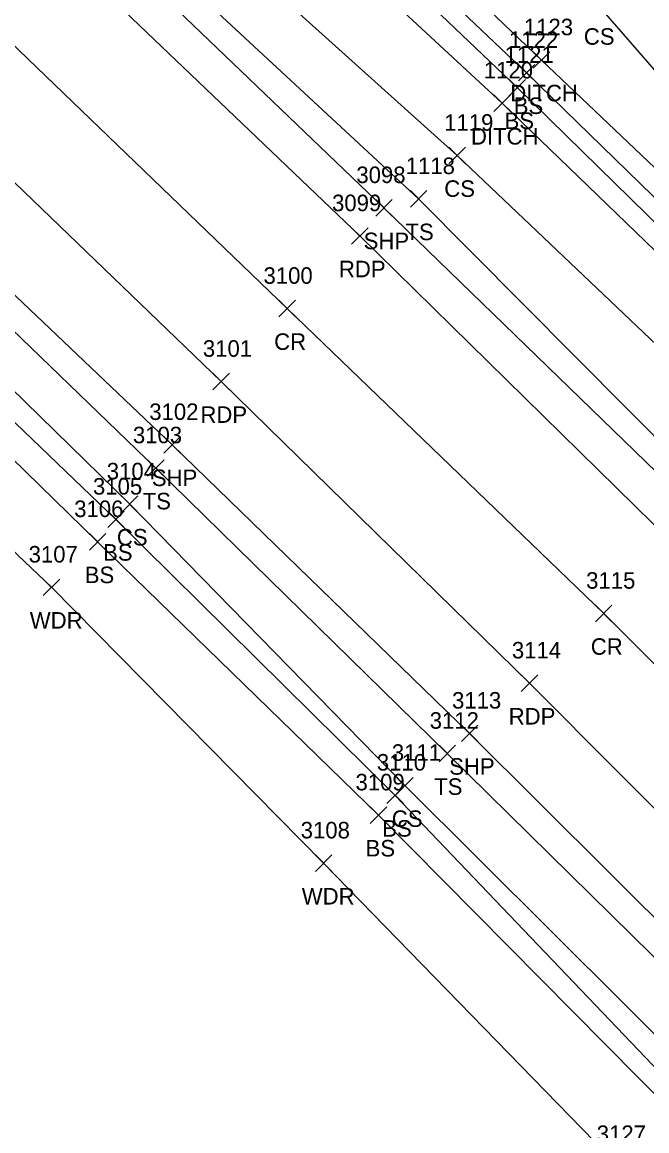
# Model space of a CAD drawing. Extents: x 1647574 to 1652703, y 212895 to 228670.
# Drawn here: x 1649743 to 1649818.5, y 226264.6 to 226398.8 of the extents above; entities that cross this region are included whole.
import ezdxf

# ---------------------------------------------------------------- set-up
doc = ezdxf.new("R2010")
doc.units = 0
for name, color, linetype in [('D_A', 7, 'Continuous'), ('D_I', 7, 'Continuous'), ('D_TIC', 7, 'Continuous'), ('DD', 7, 'Continuous'), ('L_A', 7, 'Continuous'), ('L_I', 7, 'Continuous'), ('L_TIC', 7, 'Continuous'), ('LAWA', 7, 'Continuous'), ('LELB', 7, 'Continuous'), ('P_A', 7, 'Continuous'), ('P_I', 7, 'Continuous'), ('P_TIC', 7, 'Continuous'), ('PET', 7, 'Continuous'), ('PRC', 7, 'Continuous'), ('PSP', 7, 'Continuous')]:
    doc.layers.add(name, color=color, linetype=linetype)

msp = doc.modelspace()

# ---------------------------------------------------------------- linework, layer by layer
at = {"layer": 'D_TIC'}
for points in [[(1649804.8, 226393.2), (1649806.8, 226395.2)], [(1649806.8, 226393.2), (1649804.8, 226395.2)], [(1649800.03, 226387.97), (1649802.03, 226389.97)], [(1649802.03, 226387.97), (1649800.03, 226389.97)]]:
    msp.add_lwpolyline(points, dxfattribs=at)
at = {"layer": 'DD'}
for points in [[(1649866.07, 226326.34), (1649834.51, 226356.66), (1649801.03, 226388.97), (1649771.25, 226416.61), (1649755.64, 226431), (1649757.57, 226433.02), (1649758.52, 226434.35), (1649760.18, 226436.47)], [(1649866.07, 226326.34), (1649867.38, 226328.16), (1649869, 226330.3), (1649871.11, 226331.79), (1649839.7, 226361.95), (1649805.8, 226394.2), (1649776.78, 226421.97), (1649760.18, 226436.47)]]:
    msp.add_lwpolyline(points, dxfattribs=at)
at = {"layer": 'L_TIC'}
for points in [[(1649803, 226391.67), (1649805, 226393.67)], [(1649805, 226391.67), (1649803, 226393.67)], [(1649801.88, 226389.85), (1649803.88, 226391.85)], [(1649803.88, 226389.85), (1649801.88, 226391.85)], [(1649794.6, 226381.64), (1649796.6, 226383.64)], [(1649796.6, 226381.64), (1649794.6, 226383.64)], [(1649789.94, 226376.4), (1649791.94, 226378.4)], [(1649791.94, 226376.4), (1649789.94, 226378.4)], [(1649758.16, 226343.82), (1649760.16, 226345.82)], [(1649760.16, 226343.82), (1649758.16, 226345.82)], [(1649755, 226339.45), (1649757, 226341.45)], [(1649757, 226339.45), (1649755, 226341.45)], [(1649753.34, 226337.61), (1649755.34, 226339.61)], [(1649755.34, 226337.61), (1649753.34, 226339.61)], [(1649751.12, 226334.89), (1649753.12, 226336.89)], [(1649753.12, 226334.89), (1649751.12, 226336.89)], [(1649745.55, 226329.39), (1649747.55, 226331.39)], [(1649747.55, 226329.39), (1649745.55, 226331.39)], [(1649793.41, 226309.27), (1649795.41, 226311.27)], [(1649795.41, 226309.27), (1649793.41, 226311.27)], [(1649787.1, 226304.21), (1649789.1, 226306.21)], [(1649789.1, 226304.21), (1649787.1, 226306.21)], [(1649788.26, 226305.39), (1649790.26, 226307.39)], [(1649790.26, 226305.39), (1649788.26, 226307.39)], [(1649785.09, 226301.81), (1649787.09, 226303.81)], [(1649787.09, 226301.81), (1649785.09, 226303.81)], [(1649778.45, 226296), (1649780.45, 226298)], [(1649780.45, 226296), (1649778.45, 226298)]]:
    msp.add_lwpolyline(points, dxfattribs=at)
at = {"layer": 'LAWA'}
msp.add_lwpolyline([(1649564.01, 226501.21), (1649600.78, 226471.1), (1649629.15, 226441.1), (1649657.11, 226422.45), (1649662.3, 226420.26), (1649668.81, 226414.71), (1649676.02, 226404.08), (1649707.48, 226367.52), (1649746.55, 226330.39), (1649779.45, 226297), (1649815.18, 226260.26), (1649850.99, 226223.94), (1649889.13, 226181.22), (1649919.64, 226149.68), (1649954.03, 226112.54), (1649976.77, 226080.57), (1650010.23, 226040.33), (1650031.5, 226013.99), (1650047.73, 225988.88)], dxfattribs=at)
at = {"layer": 'LELB'}
for points in [[(1650145.31, 225996.12), (1650126.11, 226017.39), (1650101.66, 226047.08), (1650074.02, 226078.27), (1650048.35, 226107.52), (1650011.02, 226148.89), (1649978.29, 226184.76), (1649948.32, 226216.56), (1649918.31, 226248.62), (1649881.09, 226286.67), (1649854.51, 226315.1), (1649822.53, 226345.57), (1649790.94, 226377.4), (1649759.46, 226406.66), (1649722.98, 226440.72), (1649699.36, 226464.18), (1649670.41, 226492.35), (1649633.05, 226526.99), (1649601.72, 226556.3), (1649565.56, 226590.44)], [(1649576.43, 226518.4), (1649614.41, 226482.98), (1649642.41, 226455.9), (1649685.38, 226415.67), (1649721.92, 226380.74), (1649759.16, 226344.82), (1649794.41, 226310.27), (1649829.09, 226276.12), (1649866.9, 226238.21), (1649900.81, 226202.84), (1649937.1, 226163.93), (1649969.44, 226128.19), (1649998.01, 226097.17), (1650029.45, 226060.68), (1650045.36, 226034.05), (1650069.99, 226009.77), (1650092.51, 225984.63), (1650111.94, 225960.02)], [(1649572.06, 226513.32), (1649610.08, 226478.23), (1649638.08, 226450.58), (1649682.17, 226412.39), (1649718, 226377.59), (1649756, 226340.45), (1649789.26, 226306.39), (1649824.84, 226270.98), (1649865.01, 226237.13), (1649898.41, 226199.96), (1649935.32, 226162.62), (1649968.54, 226127.19), (1649995.98, 226095.51), (1650026.38, 226057.31)], [(1649570.19, 226510.51), (1649608.23, 226476.35), (1649636.57, 226449.06), (1649663.19, 226421.28), (1649670.48, 226414.78), (1649679.22, 226408.18), (1649715.79, 226375.57), (1649754.34, 226338.61), (1649788.1, 226305.21), (1649822.67, 226268.96), (1649860.5, 226231.77), (1649895.97, 226193.57), (1649929.13, 226157.26), (1649962.02, 226120.66), (1649988.9, 226089.08), (1650019.8, 226051.49), (1650041.89, 226022.86), (1650059.37, 225999.62), (1650079.66, 225974.03), (1650096.25, 225946.36)], [(1650034.79, 226165.59), (1650004.25, 226206.53), (1649976.89, 226237.09), (1649942.39, 226273.76), (1649905.43, 226305.34), (1649874.8, 226336.52), (1649843.44, 226365.42), (1649812.48, 226401.05), (1649784.9, 226430.14), (1649744.52, 226461.95), (1649720.63, 226485.58), (1649711.56, 226477.85), (1649711.58, 226477.78), (1649705.42, 226471.73), (1649700.93, 226467.69), (1649709.73, 226458.24)], [(1650148.97, 226010.88), (1650139.27, 226026.59), (1650113.43, 226057), (1650088.3, 226087.98), (1650061.28, 226120.08), (1650026.24, 226159.75), (1649992.44, 226196.13), (1649963.33, 226228.07), (1649931.94, 226262.56), (1649896.29, 226297.95), (1649867.38, 226328.16), (1649836.11, 226358.29), (1649802.88, 226390.85), (1649773.49, 226418.93), (1649757.57, 226433.02), (1649733.38, 226449.67), (1649721.38, 226464.7), (1649717.89, 226468.09), (1649721.1, 226472.27), (1649725.43, 226467.47)], [(1650148.97, 226010.88), (1650154.49, 226019.63), (1650146.18, 226030.47), (1650117.14, 226060.39), (1650092.92, 226091.65), (1650065.04, 226122.85), (1650030.31, 226163.04), (1649996.06, 226198.8), (1649967.82, 226231.08), (1649935.01, 226265.64), (1649900.92, 226301.66), (1649869, 226330.3), (1649837.58, 226359.92), (1649804, 226392.67), (1649775.11, 226420.09), (1649758.52, 226434.35), (1649738.4, 226455.19), (1649725.43, 226467.47)], [(1650055.12, 226113.82), (1650017.96, 226153.32), (1649984.83, 226189.55), (1649957.12, 226222.67), (1649926.78, 226257.2), (1649885.72, 226290.18), (1649859.03, 226319.45), (1649828.58, 226351.31), (1649795.6, 226382.64), (1649764.56, 226410.62), (1649728.45, 226444.97), (1649709.73, 226458.24)], [(1649668.81, 226414.71), (1649677.68, 226406.85), (1649713.8, 226373.3), (1649752.12, 226335.89), (1649786.09, 226302.81), (1649821.42, 226267.05), (1649857.98, 226229.57), (1649894.19, 226191.19), (1649927.6, 226155.83), (1649960.21, 226119.33), (1649987.22, 226087.32), (1650018.26, 226049.98), (1650039.74, 226020.41), (1650056.73, 225997.13), (1650074.38, 225969.86), (1650089, 225939.93)]]:
    msp.add_lwpolyline(points, dxfattribs=at)
at = {"layer": 'P_TIC'}
for points in [[(1649785.75, 226375.31), (1649787.75, 226377.31)], [(1649787.75, 226375.31), (1649785.75, 226377.31)], [(1649782.82, 226371.91), (1649784.82, 226373.91)], [(1649784.82, 226371.91), (1649782.82, 226373.91)], [(1649774.04, 226363.12), (1649776.04, 226365.12)], [(1649776.04, 226363.12), (1649774.04, 226365.12)], [(1649766.06, 226354.29), (1649768.06, 226356.29)], [(1649768.06, 226354.29), (1649766.06, 226356.29)], [(1649760.14, 226346.64), (1649762.14, 226348.64)], [(1649762.14, 226346.64), (1649760.14, 226348.64)], [(1649812.32, 226326.22), (1649814.32, 226328.22)], [(1649814.32, 226326.22), (1649812.32, 226328.22)], [(1649803.34, 226317.78), (1649805.34, 226319.78)], [(1649805.34, 226317.78), (1649803.34, 226319.78)], [(1649796.11, 226311.71), (1649798.11, 226313.71)], [(1649798.11, 226311.71), (1649796.11, 226313.71)]]:
    msp.add_lwpolyline(points, dxfattribs=at)
at = {"layer": 'PET'}
for points in [[(1649568.76, 226578.15), (1649602.84, 226545.72), (1649639.6, 226511.14), (1649669.58, 226482.71), (1649710.56, 226443.02), (1649749.16, 226406.1), (1649783.82, 226372.91), (1649821.53, 226335.91), (1649854.36, 226303.39), (1649893.84, 226262.84), (1649926.53, 226228.81), (1649964.59, 226188.34), (1649995.88, 226154.08), (1650026.58, 226120.39), (1650056.63, 226086.43), (1650078.17, 226061.47), (1650102.87, 226032.97), (1650121.07, 226011.5), (1650140.46, 225987.82)], [(1649585.69, 226528.77), (1649624.3, 226492.34), (1649652.1, 226465.47), (1649694.18, 226424.93), (1649731.2, 226389.82), (1649767.06, 226355.29), (1649804.34, 226318.78), (1649837.23, 226285.73), (1649875.09, 226247.37), (1649909.48, 226211.77), (1649946.37, 226172.47), (1649978.25, 226137.54), (1650007.65, 226104.95), (1650038.73, 226069.71), (1650059.42, 226046.29), (1650084.31, 226017.14), (1650102.55, 225995.44), (1650123.3, 225970.1)]]:
    msp.add_lwpolyline(points, dxfattribs=at)
at = {"layer": 'PRC'}
msp.add_lwpolyline([(1649559.91, 226569.96), (1649593.92, 226537.25), (1649631.94, 226502.23), (1649660.46, 226474.34), (1649702.15, 226434.36), (1649740.4, 226397.48), (1649775.04, 226364.12), (1649813.32, 226327.22), (1649846.03, 226294.55), (1649884.93, 226255.04), (1649918.06, 226220.06), (1649955.14, 226180.9), (1649987.04, 226146.06), (1650016.78, 226113.16), (1650047.62, 226077.89), (1650069.26, 226053.4), (1650093.06, 226025.47), (1650111.86, 226003.86), (1650131.21, 225979.86)], dxfattribs=at)
at = {"layer": 'PSP'}
for points in [[(1649571.18, 226581.28), (1649605.62, 226548.46), (1649642.47, 226514.36), (1649673.51, 226485.11), (1649713.05, 226446.56), (1649753.13, 226408.58), (1649786.75, 226376.31), (1649825.02, 226339.17), (1649858.01, 226306.81), (1649897.5, 226266.11), (1649930.08, 226232.3), (1649968.22, 226191.53), (1649999.65, 226157.4), (1650029.99, 226123.79), (1650060.42, 226089.05), (1650081.82, 226064.3), (1650106.87, 226035.38), (1650124.34, 226014.45), (1650143.68, 225990.93)], [(1649578.75, 226520.79), (1649616.88, 226484.95), (1649644.67, 226458.4), (1649687.66, 226417.66), (1649724.18, 226382.77), (1649761.14, 226347.64), (1649797.11, 226312.71), (1649831.3, 226278.59), (1649868.9, 226240.31), (1649902.65, 226204.83), (1649939.09, 226165.73), (1649971.52, 226130.61), (1650000.21, 226098.9), (1650032.08, 226063.05), (1650053.34, 226038.39), (1650075.13, 226014.23), (1650096.57, 225988.88), (1650117.58, 225964.05)]]:
    msp.add_lwpolyline(points, dxfattribs=at)

# ---------------------------------------------------------------- texts
at = {"layer": 'D_A'}
for p in [(1649802.03, 226389.2), (1649797.27, 226383.97)]:
    msp.add_text('DITCH', height=2, dxfattribs=at).set_placement(p)
at = {"layer": 'D_I'}
for s, p in [('1123', (1649803.67, 226397.2)), ('1120', (1649798.82, 226391.97))]:
    msp.add_text(s, height=2, dxfattribs=at).set_placement(p)
at = {"layer": 'L_A'}
for s, p in [('CS', (1649810.92, 226396.05)), ('BS', (1649802.44, 226387.67)), ('BS', (1649801.33, 226385.85)), ('CS', (1649794.04, 226377.64)), ('TS', (1649789.35, 226372.4)), ('TS', (1649757.57, 226339.82)), ('CS', (1649754.45, 226335.45)), ('BS', (1649752.78, 226333.61)), ('BS', (1649750.56, 226330.89)), ('WDR', (1649743.92, 226325.39)), ('TS', (1649792.82, 226305.27)), ('CS', (1649787.7, 226301.39)), ('BS', (1649786.54, 226300.21)), ('BS', (1649784.53, 226297.81)), ('WDR', (1649776.81, 226292))]:
    msp.add_text(s, height=2, dxfattribs=at).set_placement(p)
at = {"layer": 'L_I'}
for s, p in [('1122', (1649801.87, 226395.67)), ('1121', (1649801.33, 226393.85)), ('1119', (1649794.03, 226385.64)), ('1118', (1649789.38, 226380.4)), ('3103', (1649756.39, 226347.82)), ('3104', (1649753.23, 226343.45)), ('3105', (1649751.56, 226341.61)), ('3106', (1649749.29, 226338.89)), ('3107', (1649743.78, 226333.39)), ('3112', (1649792.28, 226313.27)), ('3110', (1649785.89, 226308.21)), ('3111', (1649787.7, 226309.39)), ('3109', (1649783.31, 226305.81)), ('3108', (1649776.68, 226300)), ('3127', (1649812.48, 226263.26))]:
    msp.add_text(s, height=2, dxfattribs=at).set_placement(p)
at = {"layer": 'P_A'}
for s, p in [('SHP', (1649784.29, 226371.31)), ('RDP', (1649781.3, 226367.91)), ('CR', (1649773.47, 226359.12)), ('RDP', (1649764.55, 226350.29)), ('SHP', (1649758.68, 226342.64)), ('CR', (1649811.76, 226322.22)), ('RDP', (1649801.83, 226313.78)), ('SHP', (1649794.64, 226307.71))]:
    msp.add_text(s, height=2, dxfattribs=at).set_placement(p)
at = {"layer": 'P_I'}
for s, p in [('3098', (1649783.41, 226379.31)), ('3099', (1649780.47, 226375.91)), ('3100', (1649772.18, 226367.12)), ('3101', (1649764.85, 226358.29)), ('3102', (1649758.37, 226350.64)), ('3115', (1649811.2, 226330.22)), ('3114', (1649802.22, 226321.78)), ('3113', (1649794.98, 226315.71))]:
    msp.add_text(s, height=2, dxfattribs=at).set_placement(p)

doc.saveas('drawing.dxf')
